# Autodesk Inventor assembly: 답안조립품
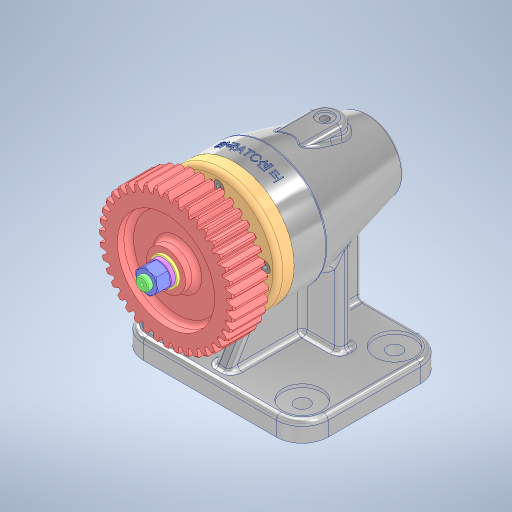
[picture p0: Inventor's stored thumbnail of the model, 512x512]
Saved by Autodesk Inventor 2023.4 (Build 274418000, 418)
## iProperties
Created: 2024-12
Part Number: 답안조립품
Document SubType Name: Assembly
Designer: EDU
Author: EDU
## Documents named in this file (14)
- C:\Users\EDU\Desktop\741204V1021\답안조립품.iam
- C:\Users\EDU\Desktop\741204V1021\본체.ipt
- C:\Users\EDU\Desktop\741204V1021\앵귤러 볼 베어링 7003A\앵귤러 볼 베어링 7003A.ipt
- C:\Users\EDU\Desktop\741204V1021\축\축.ipt
- C:\Users\EDU\Desktop\741204V1021\앵귤러 볼 제어링 7204A\앵귤러 볼 제어링 7204A.ipt
- C:\Users\EDU\Desktop\741204V1021\커버\커버.ipt
- C:\Users\EDU\Desktop\741204V1021\오일 실 20 32 8\오일 실 20 32 8.ipt
- C:\Users\EDU\Desktop\741204V1021\육각 소켓 머리 볼트 M4x10\육각 소켓 머리 볼트 M4x10.ipt
- C:\Users\EDU\Desktop\741204V1021\평행 키 4x4x14\평행 키 4x4x14.ipt
- C:\Users\EDU\Desktop\741204V1021\스퍼기어\스퍼기어.ipt
- C:\Users\EDU\Desktop\741204V1021\평와셔 M8\평와셔 M8.ipt
- C:\Users\EDU\Desktop\741204V1021\스프링 와셔 M8\스프링 와셔 M8.ipt
- C:\Users\EDU\Desktop\741204V1021\육각 너트 M8\육각 너트 M8.ipt
- C:\Users\EDU\Desktop\741204V1021\실링\실링.ipt
